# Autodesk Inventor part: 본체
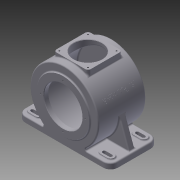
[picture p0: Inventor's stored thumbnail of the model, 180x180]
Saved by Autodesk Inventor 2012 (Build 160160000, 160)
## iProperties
Created: 2015-06
Part Number: 본체
Material: 알루미늄-6061
Document SubType Name: Modeling
Designer: Administrator
Density: 2.71 g/cm^3
Mass: 3283.63 g
Surface Area: 2303.04 cm^2
Volume: 1211.67 cm^3
Author: Administrator
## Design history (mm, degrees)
node "작업 평면2"
sketch "스케치9"
  geometry: L1 (-72, 0)-(62, 0); L2 (0, 0)-(0, 98.803); L3 (-72, 0)-(-72, 65); L4 (-72, 65)-(-59, 65); L5 (-59, 65)-(-59, 85); L6 (-59, 85)-(59, 85); L7 (59, 85)-(59, 65); L8 (59, 65)-(62, 65); L9 (62, 65)-(62, 0)
  constraints: 18 end point, 4 parallel, 4 perpendicular, 1 horizontal
  dimensions: "d23" = 72 distance from line of L2 L1.start; "d24" = 134 distance of L1.start L1.end; "d25" = 0 distance from line of L1 L2.start; "d26" = 13 distance of L3.end L4.end; "d27" = 118 distance of L5.end L6.end; "d28" = 130 diameter of L4 L1; "d29" = 170 diameter of L6 L1; "d30" = 130 diameter of L8 L1
revolve "회전2" sketch "스케치9" stored, may be unused: angle "d31" = 90 deg
sketch "스케치10"
  geometry: L1 (-115, 59)-(115, 59); L2 (115, 59)-(115, -59); L3 (115, -59)-(-115, -59); L4 (-115, -59)-(-115, 59); 2 further points
  constraints: 8 end point, 2 parallel, 1 horizontal, 1 midpoint, 1 perpendicular, 1 vertical alignment
  dimensions: "d32" = 118 distance of L3.end L1.start; "d34" = 230 distance of L1.start L1.end; "d37" = 59 distance from line of L3 point (0, 0)
extrude "돌출4" join sketch "스케치10" distance "d35" = 14; taper "d36" = 0 deg
sketch "스케치12"
  geometry: L1 (-115, -71)-(-46.733, -71) reference; L2 (46.733, -71)-(115, -71) reference; L3 (115, -85)-(115, -71) reference; L4 (-115, -85)-(115, -85) reference; L5 (-115, -85)-(-115, -71) reference; L6 (-115, -71)-(-46.733, -71) reference; L7 (-109, -71)-(-84.87, -4.703); C1 r 65 at (0, 0) reference; A1 r 85 centre (0, 0) between (46.733, -71) and (-46.733, -71) reference; A2 r 85 centre (0, 0) between (46.733, -71) and (-46.733, -71) reference; 1 further point
  constraints: 2 end point, 1 point on circle, 1 point on line
  dimensions: "d38" = 110 deg angle of L7 L1; "d39" = 6 distance from line of L7.start L5
extrude "돌출5" join sketch "스케치12" stored distance "d40" = 15; taper "d41" = 0 deg
node "작업 평면3"
sketch "스케치13"
  geometry: L1 (-42.5, 42.5)-(42.5, 42.5); L2 (42.5, 42.5)-(42.5, -42.5); L3 (42.5, -42.5)-(-42.5, -42.5); L4 (-42.5, -42.5)-(-42.5, 42.5); 3 further points
  constraints: 8 end point, 2 midpoint, 2 parallel, 1 horizontal, 1 horizontal alignment, 1 perpendicular, 1 vertical alignment
  dimensions: "d43" = 85 distance of L1.start L1.end; "d44" = 85 distance of L3.end L1.start
extrude "돌출6" join sketch "스케치13" stored distance "d45" = 15; taper "d46" = 0 deg
sketch "스케치14"
  geometry: L1 (-72, -65)-(-72, 65) reference; L2 (62, -65)-(62, 65) reference; L3 (-42.5, 88)-(42.5, 88) reference; L4 (-72, 0)-(62, 0); L5 (-64.5, 0)-(-64.5, 12); L6 (-61.5, 15)-(-61.5, 15); L7 (-61.5, 15)-(-61.5, 23.2); L8 (-61.2, 23.5)-(-48.5, 23.5); L9 (-47.5, 24.5)-(-47.5, 29.368); L10 (-47.5, 29.368)-(-49.268, 30.192); L11 (-51, 32.911)-(-51, 74); L12 (-48, 77)-(48, 77); L13 (51, 74)-(51, 47.5); L14 (51, 47.5)-(62, 47.5); L15 (-48.5, 23.5)-(-47.5, 24.5); L16 (59, -71)-(59, 85) reference; A1 r 0.3 centre (-61.2, 23.2) between (-61.2, 23.5) and (-61.5, 23.2); A2 r 3 centre (-61.5, 12) between (-61.5, 15) and (-64.5, 12); A3 r 3 centre (-48, 74) between (-48, 77) and (-51, 74); A4 r 3 centre (48, 74) between (51, 74) and (48, 77); A5 r 3 centre (-48, 32.911) between (-51, 32.911) and (-49.268, 30.192); 7 further points
  constraints: 24 end point, 14 point on line, 10 point on circle, 10 tangent, 6 parallel, 5 centre point, 3 perpendicular, 2 equal radius, 2 midpoint
  dimensions: "d47" = 154 diameter of L12 L4; "d48" = 102 distance of point (-51, 77) point (51, 77); "d50" = 95 diameter of L14 L4; "d51" = 115 deg angle of L11 L10; "d52" = 62 diameter of point (-51, 31) L4; "d53" = 14 distance of point (-61.5, 23.5) point (-47.5, 23.5); "d54" = 3 distance of point (-64.5, 15) L6.end; "d55" = 47 diameter of L8 L4; "d56" = 30 diameter of L6 L4; "d57" = 3.5 distance between parallel lines of L11 L9; "d58" = 0.3 radius of A1; "d59" = 3 radius of A2; "d60" = 1 distance of L8.end point (-47.5, 23.5); "d61" = 1 distance of L9.start point (-47.5, 23.5) (= d60); "d62" = 3 radius of A3; "d129" = 8 distance between parallel lines of L16 L13
revolve "회전3" sketch "스케치14" stored, may be unused: angle "d63" = 90 deg
chamfer "모따기1" distance "d64" = 1; stored, may be unused: second distance "d65" = 2, angle "d66" = 45 deg
sketch "스케치15"
  geometry: C1 r 35 at (0, 0); 1 further point
  constraints: 1 centre point, 1 coincident
  dimensions: "d67" = 70 diameter of C1
extrude "돌출7" cut sketch "스케치15" distance "d68" = 50; taper "d69" = 0 deg
fillet "모깎기1" dims "d70" = 3
chamfer "모따기2" distance "d71" = 1; stored, may be unused: second distance "d72" = 2, angle "d73" = 45 deg
sketch "스케치16"
  geometry: C1 r 36 at (0, 0) reference; 4 further points
  constraints: 2 horizontal alignment, 2 vertical alignment
  dimensions: "d74" = 71 distance of point (-35.5, -35.5) point (-35.5, 35.5); "d75" = 35.5 horizontal distance of C1.centre point (-35.5, 35.5); "d76" = 71 distance of point (35.5, 35.5) point (-35.5, 35.5) (= d74); "d77" = 35.5 horizontal distance of point (-35.5, 35.5) C1.centre (= d75)
hole "구멍1" sketch "스케치16" at (-35.5, 35.5), (-35.5, -35.5), (35.5, 35.5), (35.5, -35.5) diameter "d78" = 3.242; stored, may be unused: countersink angle "d82" = 90 deg, drill point angle "d84" = 118 deg; dims "d79" = 10, "d80" = 4, "d81" = 2, "d83" = 13
sketch "스케치17"
  geometry: L1 (115, -59)-(46.733, -59) reference; L2 (115, 59)-(115, -59) reference; L3 (97, -45)-(81, -45); L4 (97, -37)-(81, -37); A1 r 4 centre (97, -41) between (97, -45) and (97, -37); A2 r 4 centre (81, -41) between (81, -37) and (81, -45); 1 further point
  constraints: 4 end point, 4 point on circle, 4 tangent, 2 centre point, 1 horizontal alignment
  dimensions: "d85" = 8 diameter of A1; "d86" = 8 diameter of A2; "d87" = 16 distance of A2.centre A1.centre; "d88" = 18 distance from line of A1.centre L2; "d89" = 18 distance from line of A1.centre L1
extrude "돌출8" cut sketch "스케치17" distance "d90" = 50; taper "d91" = 0 deg
sketch "스케치18"
  geometry: L1 (81, -37)-(97, -37) reference; L2 (97, -45)-(81, -45) reference; L3 (81, -32)-(97, -32); L4 (81, -50)-(97, -50); A1 r 4 centre (97, -41) between (97, -45) and (97, -37) reference; A2 r 4 centre (81, -41) between (81, -37) and (81, -45) reference; A3 r 9 centre (97, -41) between (88.938, -45) and (89, -45.123); A4 r 9 centre (81, -41) between (89, -45.123) and (89.062, -45); A5 r 9 centre (97, -41) between (97, -50) and (97, -32); A6 r 9 centre (97, -41) between (89, -36.877) and (88.938, -37); A7 r 9 centre (81, -41) between (89.062, -37) and (89, -36.877); A8 r 9 centre (81, -41) between (81, -32) and (81, -50); 1 further point
  constraints: 12 point on circle, 6 centre point, 4 end point, 4 point on line, 3 tangent, 2 coincident, 1 parallel
  dimensions: "d94" = 9 radius of A8; "d95" = 9 radius of A5 (= d94)
extrude "돌출9" join sketch "스케치18" distance "d96" = 3; taper "d97" = 0 deg
fillet "모깎기2" dims "d98" = 3
fillet "모깎기3" dims "d105" = 18
sketch "스케치19"
  geometry: C1 r 65 at (0, 0) reference; 1 further point
  constraints: 1 vertical alignment
  dimensions: "d106" = 55 distance of C1.centre point (0, 55)
hole "구멍2" sketch "스케치19" at (0, 55) diameter "d107" = 3.242; stored, may be unused: countersink angle "d111" = 90 deg, drill point angle "d113" = 118 deg; dims "d108" = 10, "d109" = 4, "d110" = 2, "d112" = 13
fillet "모깎기4" dims "d117" = 3
fillet "모깎기5" dims "d118" = 7
fillet "모깎기6" dims "d119" = 3
node "작업 평면8"
  node "작업 평면6"
sketch "스케치22"
  geometry: 2 further points
  constraints: 1 coincident, 1 other
  dimensions: "d126" = 0 distance of point (0, 0) point (0, 0)
feature "엠보싱1" sketch "스케치22" dims "d23" = 72, "d24" = 134, "d25" = 0, "d26" = 13, "d27" = 118, "d28" = 130, "d29" = 170, "d30" = 130, "d127" = 0.5, "d128" = 0
node "솔리드3"
mirror "대칭1"
pattern_linear "직사각형 패턴1" dims "d101" = 178, "d104" = 82
pattern_circular "원형 패턴1" dims angle "d115" = 360 deg
node "투영된 루프2"
other parameters: "d17" = -85, "d42" = 173, "d92" = 18, "d93" = 18, "d122" = 295 deg, "d125" = 85
